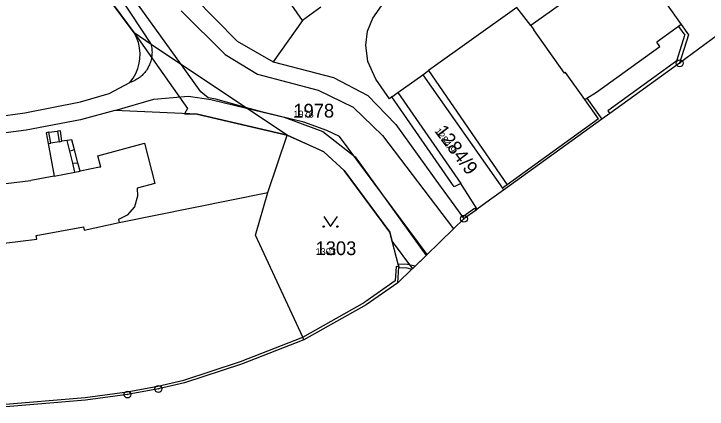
# Model space of a CAD drawing. Extents: x -763628 to -761565, y -976033 to -973833.
# Drawn here: x -762052.9 to -761951.7, y -975491 to -975433.4 of the extents above; entities that cross this region are included whole.
import ezdxf

# ---------------------------------------------------------------- set-up
doc = ezdxf.new("R2010")
doc.units = 0
for name, color, linetype in [('KN_cisla parcel 1000', 7, 'Continuous'), ('KN_cisla parcel 500', 7, 'Continuous'), ('KN_hranice parcel', 7, 'Continuous'), ('KN_hranice uzemi', 7, 'Continuous'), ('KN_vecna bremena', 7, 'Continuous'), ('KN_vnitrni kresba parcel', 7, 'Continuous'), ('KN_znacky bodu BP', 7, 'Continuous'), ('KN_znacky kultur', 7, 'Continuous')]:
    doc.layers.add(name, color=color, linetype=linetype)

msp = doc.modelspace()

# ---------------------------------------------------------------- linework, layer by layer
at = {"layer": 'KN_hranice parcel'}
for p, q in [((-762035.36, -975436.14), (-762041.64, -975427.64)), ((-762015.83, -975459.42), (-762013.02, -975451.08))]:
    msp.add_line(p, q, dxfattribs=at)
for points in [[(-762044.03, -975404.74), (-762042.1, -975409.36), (-762039.14, -975414.15), (-762033.69, -975421.45), (-762026.63, -975430.9), (-762020.3, -975437.39), (-762015.06, -975440.37), (-762006.25, -975442.66), (-762001.25, -975445.29), (-761997.18, -975449.55), (-761990.69, -975458.51), (-761989.1, -975460.7), (-761987.43, -975463), (-761987.23, -975463.28)], [(-762001.52, -975437.94), (-762001.3, -975435.9), (-762000.53, -975434.04), (-761998.56, -975431.2), (-762001.32, -975427.14), (-761989.36, -975418.59)], [(-761962.58, -975425.5), (-761966.14, -975427.98), (-761966.57, -975427.32), (-761977.48, -975435.11), (-761979.52, -975432.45), (-761992.39, -975441.67)], [(-762122.11, -975433.86), (-762117.95, -975436.47), (-762108.14, -975441.1), (-762097.88, -975444.86), (-762087.93, -975447.3), (-762077.23, -975448.86), (-762066.66, -975449.25), (-762056.98, -975448.58), (-762051.29, -975447.83), (-762043.18, -975446.24), (-762038.98, -975445.01), (-762035.97, -975443.4)], [(-762035.97, -975443.4), (-762035.5, -975442.76), (-762035.11, -975442.07), (-762034.81, -975441.34), (-762034.61, -975440.57), (-762034.51, -975439.95), (-762034.49, -975439.16), (-762034.56, -975438.37), (-762034.73, -975437.59), (-762035, -975436.85), (-762035.36, -975436.14)], [(-762013.02, -975451.08), (-762018.95, -975447.13), (-762032.89, -975437.85), (-762035.36, -975436.14)], [(-761997.74, -975445.49), (-761998.11, -975445.76), (-762000.09, -975442.92), (-762001.23, -975440.34), (-762001.52, -975437.94)], [(-761997.74, -975445.49), (-761996.88, -975444.88), (-761993.24, -975442.27), (-761992.39, -975441.67)], [(-761992.39, -975441.67), (-761980.92, -975458.3), (-761981.62, -975458.8), (-761981.44, -975459.11)], [(-761985.28, -975461.88), (-761987.68, -975458.11), (-761988.63, -975458.63), (-761997.74, -975445.49)], [(-762013.02, -975451.08), (-762026.15, -975448.04), (-762038.16, -975447.47), (-762043.16, -975448.84), (-762051.1, -975450.34), (-762056.72, -975451.07), (-762066.57, -975451.72), (-762077.26, -975451.35), (-762088.41, -975449.8), (-762098.15, -975447.42), (-762099.12, -975447.07)], [(-761996.87, -975472.63), (-761996.74, -975470.26), (-761998.05, -975465.24), (-762004.71, -975456.21), (-762007.68, -975453.49), (-762013.02, -975451.08)], [(-762103.85, -975462.29), (-762099.19, -975463.7), (-762099.03, -975463.16), (-762092.27, -975464.76), (-762092.36, -975465.3), (-762087.56, -975466.12), (-762082.8, -975466.88), (-762082.71, -975466.34), (-762075.81, -975466.96), (-762075.82, -975467.51), (-762070.97, -975467.65), (-762066.15, -975467.73), (-762066.14, -975467.2), (-762059.18, -975466.84), (-762059.12, -975467.38), (-762054.32, -975466.83), (-762049.53, -975466.27), (-762049.64, -975465.72), (-762042.75, -975464.44), (-762042.65, -975464.95), (-762037.55, -975463.83), (-762015.83, -975459.42)], [(-762010.57, -975480.92), (-762010.74, -975480.56), (-762017.66, -975465.68), (-762015.83, -975459.42)]]:
    msp.add_lwpolyline(points, dxfattribs=at)
at = {"layer": 'KN_hranice uzemi'}
msp.add_line((-761935.32, -975425.39), (-761955.76, -975440.6), dxfattribs=at)
for points in [[(-761955.76, -975440.6), (-761965.94, -975447.93), (-761967.1, -975448.77), (-761981.44, -975459.11)], [(-761981.44, -975459.11), (-761983.48, -975460.58), (-761985.28, -975461.88)], [(-761985.28, -975461.88), (-761985.46, -975462.01), (-761987.23, -975463.28)], [(-761987.23, -975463.28), (-761988.73, -975464.74), (-761992.73, -975468.62), (-761994.36, -975470.2), (-761994.82, -975470.64), (-761996.87, -975472.63)], [(-761996.87, -975472.63), (-762001.5, -975475.8), (-762010.57, -975480.92)], [(-762010.57, -975480.92), (-762019.69, -975484.46), (-762028.01, -975487.2), (-762031.81, -975488.09), (-762036.33, -975488.9), (-762042.43, -975489.72), (-762058.16, -975491.03)]]:
    msp.add_lwpolyline(points, dxfattribs=at)
at = {"layer": 'KN_vecna bremena'}
msp.add_lwpolyline([(-762048.42, -975418.46), (-762035.36, -975436.14), (-762027.57, -975447.19), (-762027.99, -975447.95), (-762026.15, -975448.04), (-762013.02, -975451.08), (-762008.36, -975453.18), (-762007.68, -975453.49), (-762007.02, -975454.1), (-762004.71, -975456.21), (-761998.05, -975465.24), (-761997.69, -975466.61), (-761994.74, -975470.57), (-761992.58, -975468.47), (-762005.39, -975451.26), (-762007.21, -975450.39), (-762010.61, -975449.21), (-762016.59, -975447.71), (-762019.1, -975447.03), (-762023.45, -975445.85), (-762024.57, -975445.64), (-762025.61, -975444.77), (-762028.45, -975440.81), (-762036.84, -975429.09)], dxfattribs=at)
msp.add_lwpolyline([(-761996.75, -975470.38), (-761995.56, -975470.44), (-761994.82, -975470.64), (-761994.36, -975470.2), (-761995.46, -975469.92), (-761996.84, -975469.87), (-761996.74, -975470.26)], close=True, dxfattribs=at)
at = {"layer": 'KN_vnitrni kresba parcel'}
for p, q in [((-762047.45, -975415.67), (-762032.89, -975437.85)), ((-762010.79, -975434.34), (-762020.3, -975420.76)), ((-761957.8, -975431.73), (-761955.52, -975434.94)), ((-762028.49, -975432.93), (-762022.09, -975439.34)), ((-762008.11, -975432.43), (-762010.79, -975434.34)), ((-762010.79, -975434.34), (-762015.06, -975440.37)), ((-761977.48, -975435.11), (-761977.05, -975435.71)), ((-761955.93, -975435.23), (-761959.07, -975437.51)), ((-761955.52, -975434.94), (-761955.93, -975435.23)), ((-761955.93, -975435.23), (-761955.01, -975436.51)), ((-761955.52, -975434.94), (-761954.45, -975436.44)), ((-761972.53, -975442.04), (-761977.05, -975435.71)), ((-761956.14, -975440.26), (-761955.01, -975436.51)), ((-761954.45, -975436.44), (-761955.76, -975440.6)), ((-761967.9, -975444.8), (-761958.64, -975438.17)), ((-761958.64, -975438.17), (-761959.07, -975437.51)), ((-762022.09, -975439.34), (-762017.35, -975442.19)), ((-761956.14, -975440.26), (-761966.23, -975447.52)), ((-762017.35, -975442.19), (-762008.52, -975444.53)), ((-761993.24, -975442.27), (-761981.62, -975458.8)), ((-761972.41, -975441.96), (-761972.53, -975442.04)), ((-761969.61, -975445.87), (-761972.41, -975441.96)), ((-762032.5, -975445.84), (-762027.4, -975445.4)), ((-762027.4, -975445.4), (-762024.18, -975445.89)), ((-762008.52, -975444.53), (-762003.41, -975447.02)), ((-761996.88, -975444.88), (-761987.68, -975458.11)), ((-761969.3, -975445.68), (-761967.9, -975444.8)), ((-762038.16, -975447.47), (-762032.5, -975445.84)), ((-762024.18, -975445.89), (-762018.95, -975447.13)), ((-761969.61, -975445.87), (-761969.3, -975445.68)), ((-761967.58, -975448.69), (-761969.61, -975445.87)), ((-761969.3, -975445.68), (-761967.1, -975448.77)), ((-762018.95, -975447.13), (-762013.45, -975448.44)), ((-762003.41, -975447.02), (-761999.13, -975451.11)), ((-762013.45, -975448.44), (-762007.83, -975450.53)), ((-761966.23, -975447.52), (-761965.94, -975447.93)), ((-761967.58, -975448.69), (-761980.92, -975458.3)), ((-762047.79, -975450.66), (-762046.51, -975450.5)), ((-762046.12, -975450.44), (-762046.51, -975450.5)), ((-762046.51, -975450.5), (-762046.27, -975452.03)), ((-762045.88, -975451.97), (-762046.12, -975450.44)), ((-762007.83, -975450.53), (-762003.08, -975454.25)), ((-762047.79, -975450.66), (-762048.18, -975450.74)), ((-762048.18, -975450.74), (-762047.89, -975452.29)), ((-762047.5, -975452.23), (-762047.79, -975450.66)), ((-761999.13, -975451.11), (-761988.73, -975464.74)), ((-762047.89, -975452.29), (-762047.5, -975452.23)), ((-762047.89, -975452.29), (-762047.01, -975457.05)), ((-762046.27, -975452.03), (-762047.5, -975452.23)), ((-762046.27, -975452.03), (-762045.88, -975451.97)), ((-762045.1, -975451.85), (-762045.88, -975451.97)), ((-762044.42, -975451.75), (-762045.1, -975451.85)), ((-762044.73, -975453.4), (-762045.1, -975451.85)), ((-762044.04, -975453.24), (-762044.42, -975451.75)), ((-762040.66, -975454.11), (-762033.83, -975452.27)), ((-762033.83, -975452.27), (-762032.35, -975458.12)), ((-762044.04, -975453.24), (-762044.73, -975453.4)), ((-762044.32, -975455.15), (-762044.73, -975453.4)), ((-762043.56, -975455.11), (-762044.04, -975453.24)), ((-762040.21, -975455.73), (-762040.66, -975454.11)), ((-762003.08, -975454.25), (-761992.73, -975468.62)), ((-762044.32, -975455.15), (-762043.56, -975455.11)), ((-762044.01, -975456.47), (-762044.32, -975455.15)), ((-762043.25, -975456.32), (-762043.56, -975455.11)), ((-762047.01, -975457.05), (-762044.01, -975456.47)), ((-762044.01, -975456.47), (-762043.25, -975456.32)), ((-762040.41, -975455.77), (-762043.25, -975456.32)), ((-762040.21, -975455.73), (-762040.41, -975455.77)), ((-762047.01, -975457.05), (-762050.41, -975457.71)), ((-762060.12, -975458.87), (-762050.41, -975457.71)), ((-762032.35, -975458.12), (-762034.93, -975458.79)), ((-762034.93, -975458.79), (-762034.84, -975459.97)), ((-762034.84, -975459.97), (-762035.28, -975461.53)), ((-762035.28, -975461.53), (-762036.35, -975462.75)), ((-761987.43, -975463), (-761985.67, -975461.72)), ((-761985.67, -975461.72), (-761985.46, -975462.01)), ((-762036.35, -975462.75), (-762037.63, -975463.39)), ((-762037.63, -975463.39), (-762037.55, -975463.83)), ((-761997.14, -975470.24), (-761997.26, -975472.34)), ((-761996.74, -975470.26), (-761997.14, -975470.24)), ((-761997.26, -975472.34), (-762001.7, -975475.45)), ((-762010.74, -975480.56), (-762001.7, -975475.45)), ((-762019.81, -975484.08), (-762010.74, -975480.56)), ((-762028.1, -975486.81), (-762019.81, -975484.08)), ((-762031.9, -975487.7), (-762028.1, -975486.81)), ((-762036.38, -975488.5), (-762031.9, -975487.7)), ((-762042.48, -975489.32), (-762036.38, -975488.5)), ((-762058.19, -975490.63), (-762042.48, -975489.32))]:
    msp.add_line(p, q, dxfattribs=at)
msp.add_lwpolyline([(-762032.89, -975437.85), (-762032.85, -975438.03), (-762032.81, -975438.22), (-762032.78, -975438.41), (-762032.76, -975438.6), (-762032.75, -975438.78), (-762032.74, -975438.97), (-762032.75, -975439.16), (-762032.76, -975439.35), (-762032.78, -975439.54), (-762032.8, -975439.73), (-762032.84, -975439.91), (-762032.88, -975440.1), (-762032.93, -975440.28), (-762032.98, -975440.46), (-762033.04, -975440.64), (-762033.11, -975440.82), (-762033.19, -975440.99), (-762033.28, -975441.16), (-762033.37, -975441.32), (-762033.47, -975441.48), (-762033.57, -975441.64), (-762033.69, -975441.79), (-762033.8, -975441.94), (-762033.93, -975442.09), (-762034.06, -975442.22), (-762034.19, -975442.36), (-762034.33, -975442.48), (-762034.48, -975442.6), (-762034.63, -975442.72), (-762034.78, -975442.83), (-762034.94, -975442.93), (-762035.1, -975443.03), (-762035.27, -975443.11), (-762035.44, -975443.2), (-762035.61, -975443.27), (-762035.79, -975443.34), (-762035.97, -975443.4)], dxfattribs=at)
at = {"layer": 'KN_znacky bodu BP'}
for centre, radius in [((-761955.76, -975440.6), 0.5), ((-761955.76, -975440.6), 0.0303), ((-761987.23, -975463.28), 0.5), ((-761987.23, -975463.28), 0.0303), ((-762031.81, -975488.09), 0.5), ((-762036.33, -975488.9), 0.5), ((-762036.33, -975488.9), 0.0303), ((-762031.81, -975488.09), 0.0303)]:
    msp.add_circle(centre, radius, dxfattribs=at)
at = {"layer": 'KN_znacky kultur'}
msp.add_lwpolyline([(-762007.68, -975462.92), (-762006.68, -975464.42), (-762005.68, -975462.92)], dxfattribs=at)
for centre in [(-762007.68, -975464.42), (-762005.68, -975464.42)]:
    msp.add_circle(centre, 0.1, dxfattribs=at)

# ---------------------------------------------------------------- texts
at = {"layer": 'KN_cisla parcel 1000'}
for s, p in [('1978', (-762012.12, -975448.51)), ('1303', (-762008.88, -975468.57))]:
    msp.add_text(s, height=2, dxfattribs=at).set_placement(p)
msp.add_text('1284/9', height=2, rotation=307, dxfattribs=at).set_placement((-761991.57, -975450.52))
at = {"layer": 'KN_cisla parcel 500'}
for s, p in [('1978', (-762012.12, -975448.51)), ('1303', (-762008.88, -975468.57))]:
    msp.add_text(s, height=1, dxfattribs=at).set_placement(p)
msp.add_text('1284/9', height=1, rotation=307, dxfattribs=at).set_placement((-761991.57, -975450.52))

doc.saveas('drawing.dxf')
